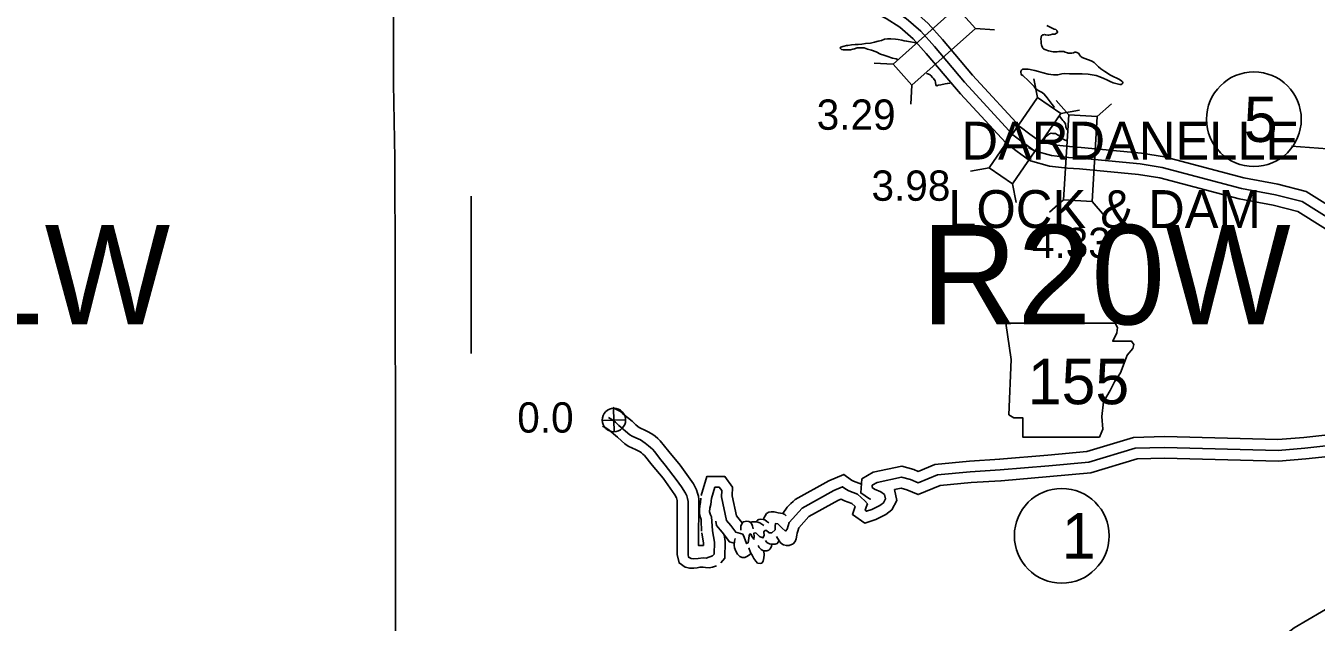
# Model space of a CAD drawing. Extents: x 31699 to 244310, y -8841 to 11474.
# Drawn here: x 94816 to 96015, y 3295 to 3849 of the extents above; entities that cross this region are included whole.
import ezdxf

# ---------------------------------------------------------------- set-up
doc = ezdxf.new("R2010")
doc.units = 0
for name, color, linetype in [('B_Logo', 7, 'Continuous'), ('Default', 7, 'Continuous'), ('G-ANNO-TEXT', 7, 'Continuous'), ('Level 21', 7, 'Continuous'), ('Level 55', 7, 'Continuous'), ('R_Border', 7, 'Continuous'), ('R_Border Notes', 7, 'Continuous'), ('R_Draft', 7, 'Continuous'), ('R_Logo', 7, 'Continuous'), ('R_XS_EARTHWORK_STAGE1', 7, 'Continuous'), ('R_XS_EARTHWORK_STAGE2', 7, 'Continuous'), ('S_WALL', 7, 'Continuous'), ('S_WALL_ANNOT', 7, 'Continuous')]:
    doc.layers.add(name, color=color, linetype=linetype)

msp = doc.modelspace()

# ---------------------------------------------------------------- linework, layer by layer
at = {"layer": 'B_Logo'}
for points in [[(95753.4, 3733), (95743, 3740.4), (95733.2, 3747.8), (95691.9, 3792.7), (95688.3, 3796.7), (95660.2, 3830.1), (95647.5, 3844.3), (95634.1, 3856), (95620.4, 3864.7), (95590.5, 3879.8), (95576.9, 3888.3), (95551.3, 3907.5), (95539.3, 3920.6), (95516.6, 3952.1), (95510.9, 3959.9), (95506.1, 3965.2), (95496.6, 3971.7), (95443.3, 3997.1)], [(95747.7, 3736.2), (95753.4, 3733), (95769.1, 3728.7), (95784.9, 3726.9), (95795.9, 3726.2), (95851.3, 3720.9), (95871.9, 3717.6), (95945.7, 3698.1), (95977.2, 3692.1), (96001.9, 3685.9), (96046.9, 3657.8)], [(95357.4, 3485.3), (95360.6, 3483.3), (95364, 3480.7), (95367.2, 3477.8), (95377.4, 3469), (95379.3, 3467.8), (95383, 3466.2), (95387.2, 3464.3), (95391.6, 3461.4), (95394.6, 3458.9), (95398.4, 3455.7), (95400.6, 3453.1), (95404.9, 3447.3), (95410.2, 3440.8), (95420.3, 3427.6), (95425.3, 3420.7), (95429.1, 3414.7), (95430.1, 3412.4), (95431, 3410), (95431.4, 3407), (95431.6, 3357.7), (95431.9, 3355.2), (95434.4, 3354), (95436.6, 3353.8), (95440.8, 3354.2), (95445.5, 3354.8), (95448.1, 3354.5), (95454.1, 3356.6)], [(95721.5, 3436.4), (95766.6, 3440.3), (95803.7, 3443.5), (95846.9, 3456.7), (95873.9, 3457.4), (95979.7, 3454.5), (96004.5, 3456.6), (96049, 3461.5), (96069.2, 3461.7), (96138.5, 3454.2), (96224.1, 3446.2), (96261.8, 3440.7), (96280.3, 3437.6)], [(95721.5, 3436.4), (95693.6, 3434.6), (95663.1, 3431.8), (95645.2, 3424.3), (95637.9, 3427.4), (95629.8, 3429.7), (95607, 3424.8), (95602.4, 3422.2), (95602.3, 3420.1), (95604.6, 3418.5), (95610.4, 3416.1), (95614, 3413.5), (95614.9, 3409.5), (95612.9, 3405.9), (95609.7, 3403.4), (95602, 3399.5), (95597.3, 3398), (95596, 3398.9), (95596.9, 3401.7), (95598, 3404.9), (95595.5, 3407.8), (95588.8, 3414), (95580.8, 3416.9), (95578, 3418.4), (95574.8, 3420.8), (95566.7, 3417.2), (95537.3, 3401), (95525.3, 3387.5), (95523.6, 3381.4), (95521.9, 3379.6), (95518.6, 3382.7), (95514.9, 3386.2), (95512.6, 3386.5), (95512.2, 3384.4), (95512.4, 3380.8), (95509.3, 3378.1), (95506.8, 3378.1), (95504.2, 3380), (95502.8, 3380.1), (95501.9, 3379), (95502.2, 3375.5), (95500.9, 3373.2), (95497.6, 3374.6), (95494.4, 3377.9), (95492.5, 3377.8), (95492.9, 3374.6), (95492.6, 3372), (95490.7, 3374.4), (95490.1, 3376.5), (95488.9, 3377), (95488, 3375.3), (95487.2, 3368.7), (95485.8, 3368), (95483.5, 3374), (95482.2, 3376.8), (95475.7, 3378.5), (95471, 3384.7), (95467.2, 3389.4), (95462.5, 3411.3), (95462.6, 3417.2), (95460.3, 3420.4), (95456.3, 3420.4), (95453.1, 3409.9)], [(95453.1, 3410.2), (95452.4, 3404.4), (95451.6, 3400.9), (95451.2, 3397.4), (95452.2, 3394.6), (95453, 3392.8), (95454, 3380)], [(95454, 3379.7), (95455.9, 3369.3), (95455.5, 3358.2), (95454.1, 3356.6)]]:
    msp.add_lwpolyline(points, dxfattribs=at)
at = {"layer": 'Default'}
msp.add_line((95229.9, 3691), (95229.9, 3544.7), dxfattribs=at)
at = {"layer": 'G-ANNO-TEXT'}
msp.add_lwpolyline([(95726.6, 3572.9), (95731.7, 3539), (95729.5, 3487.7), (95734, 3484.9), (95742.4, 3484.9), (95742.4, 3466.9), (95813.5, 3466.9), (95816.9, 3474.2), (95815.7, 3486), (95817.4, 3499.6), (95823.6, 3510.3), (95827.6, 3518.2), (95833.2, 3526.6), (95836.6, 3535.7), (95839.4, 3543), (95844.5, 3549.2), (95845.6, 3553.1), (95843.4, 3556), (95825.9, 3556), (95829.8, 3563.9), (95830.4, 3568.9), (95828.1, 3572.8)], close=True, dxfattribs=at)
at = {"layer": 'Level 21'}
for p, q in [((95362.7, 3471.9), (95362.2, 3493.6)), ((95351.6, 3482.5), (95373.3, 3483))]:
    msp.add_line(p, q, dxfattribs=at)
msp.add_circle((95362.5, 3482.8), 10.9, dxfattribs=at)
at = {"layer": 'Level 55'}
for points in [[(95445.7, 3366.2), (95444.2, 3366.2), (95441.4, 3366.1), (95441.2, 3366.1), (95441.5, 3409), (95441.2, 3412.1), (95440.2, 3414.7), (95439.2, 3417.9), (95436.5, 3423.5), (95424, 3440.9), (95413.6, 3453.6), (95405.5, 3463.4), (95403.2, 3465.6), (95400.9, 3467.8), (95397.8, 3470), (95393.8, 3472.2), (95390.6, 3473.8), (95387.9, 3474.9), (95386.1, 3475.8), (95384.7, 3476.7), (95382.9, 3478.3), (95379.3, 3481.8), (95370.9, 3488.7), (95368.1, 3491), (95364.3, 3493), (95361.4, 3494.6)], [(95457.7, 3347.3), (95456, 3346.6), (95454.2, 3346.1), (95451, 3345.5), (95447.6, 3345.8), (95445.5, 3346.1), (95444.1, 3346.2), (95443.7, 3346.2), (95442.2, 3345.9), (95439.8, 3345.4), (95436.8, 3345), (95433, 3345.1), (95428.8, 3346.1), (95423, 3350), (95421.2, 3357.9), (95421.4, 3407.8), (95421.3, 3408.1), (95420.6, 3410.5), (95419.2, 3413.3), (95408.2, 3428.7), (95398.1, 3440.9), (95390.8, 3449.8), (95389.5, 3451.1), (95388.2, 3452.3), (95387, 3453.1), (95384.5, 3454.5), (95382.6, 3455.5), (95379.7, 3456.6), (95375.8, 3458.6), (95372.6, 3460.7), (95369.4, 3463.5), (95365.9, 3466.9), (95358.1, 3473.3), (95356.9, 3474.3), (95354.9, 3475.4), (95351.8, 3477)], [(95720.9, 3446.4), (95692.9, 3444.6), (95660.7, 3441.6), (95645.2, 3435.1), (95641.2, 3436.8), (95630.1, 3440), (95603.3, 3434.3), (95592.8, 3428.1), (95591.9, 3415.1), (95599.8, 3409.6), (95601.3, 3409.1)], [(95481.7, 3387.2), (95481.6, 3387.3), (95478.9, 3390.8), (95476.5, 3393.8), (95472.5, 3412.4), (95472.6, 3420.3), (95465.6, 3430.3), (95448.9, 3430.4), (95443.5, 3412.8)], [(95592.4, 3423.3), (95585, 3426.1), (95583.3, 3426.9), (95576, 3432.2), (95562.3, 3426.2), (95530.9, 3408.9)], [(95722.1, 3426.4), (95694.4, 3424.7), (95665.6, 3422), (95645.2, 3413.5), (95634.6, 3417.9), (95629.4, 3419.4), (95623.2, 3418.1), (95625.5, 3408.1), (95620.7, 3399.3), (95615.1, 3394.9), (95605.8, 3390.2), (95595.6, 3387), (95584.1, 3395), (95586.6, 3402.4), (95583.5, 3405.3), (95576.7, 3407.8), (95573.7, 3409.4), (95571.1, 3408.3), (95543.6, 3393.1)], [(95443.1, 3410.1), (95442.9, 3406), (95442.2, 3403.2), (95442, 3399.7), (95442, 3396), (95442.8, 3392.2), (95443.5, 3390.5), (95443.7, 3389.5), (95444, 3379.5)], [(95530.9, 3408.9), (95528.9, 3407.2), (95526.9, 3405.3), (95523.6, 3401.7), (95519.4, 3395.9)], [(95522.5, 3393.7), (95521.3, 3394.9), (95519.4, 3395.9), (95515.1, 3396.7), (95511.3, 3397.5), (95508.8, 3397.6), (95506.3, 3397.1), (95504.2, 3395.9), (95503, 3393.9), (95501.8, 3391.6), (95501.5, 3390.3)], [(95543.6, 3393.1), (95534.3, 3382.6)], [(95474.3, 3368.5), (95469.8, 3369.7), (95463.1, 3378.5), (95457.9, 3384.9), (95457.1, 3388.8)], [(95489, 3387.9), (95487.7, 3388.6), (95486.1, 3388.7), (95484.5, 3388.6), (95482.7, 3388.1), (95481.2, 3386.3), (95480.5, 3384.2), (95480.4, 3383), (95480.4, 3380.3)], [(95489, 3387.9), (95489.7, 3387.3), (95490.7, 3385.9), (95491.4, 3384.1), (95492, 3381.7)], [(95501.7, 3384.7), (95499.9, 3386.1), (95498.1, 3387.2), (95496.3, 3387.8), (95494.6, 3388.1), (95492.6, 3388.2), (95490.7, 3388.2), (95489.3, 3387.9)], [(95506.3, 3387.3), (95504.7, 3388.6), (95502.7, 3390.1), (95501.3, 3390.5), (95499.1, 3390.8), (95497.2, 3390.5), (95495.8, 3389.8), (95494.7, 3388.6), (95494.5, 3388)], [(95534.3, 3382.6), (95533.4, 3379.6), (95532.7, 3377.7), (95532.3, 3375.9), (95531.9, 3372.5), (95530.9, 3369.8), (95528.9, 3367.8), (95525.4, 3366.3), (95522.8, 3366.1), (95520.2, 3366.7), (95517.6, 3368.5), (95515.9, 3370.4), (95513.4, 3374.4)], [(95444.1, 3377.9), (95445.8, 3368.5), (95445.8, 3366.2)], [(95464.8, 3376.1), (95465.9, 3370), (95465.4, 3354.4), (95461.7, 3350.1)], [(95489.9, 3358.9), (95488.8, 3357.7), (95486.6, 3356.2), (95484.1, 3355.1), (95481.6, 3355.1), (95479.5, 3356.1), (95477.4, 3358.2), (95475.7, 3361), (95474.6, 3363.9), (95474.3, 3366.6), (95474.5, 3370.3), (95475.1, 3372.6)], [(95515.8, 3370.5), (95515.2, 3369.3), (95514.3, 3368.1), (95512.4, 3367.4), (95510.8, 3367.4), (95508.3, 3367.3), (95506.9, 3367.8), (95504.6, 3369.1), (95503.4, 3370.9)], [(95501.9, 3361), (95502, 3357.4), (95501.8, 3354.8), (95501.1, 3351.7), (95499.9, 3349.9), (95498.4, 3349.6), (95496, 3349.9), (95494.3, 3351.5), (95492.4, 3354.1), (95490.9, 3357.1), (95489.5, 3359.8), (95487.9, 3364)], [(95509.1, 3367.2), (95508.8, 3365.5), (95508.4, 3364), (95507.4, 3362.7), (95506.3, 3361.8), (95504.5, 3361.1), (95502.6, 3361.1), (95500.8, 3361.6), (95499.3, 3362.5), (95497.4, 3364.4), (95496.6, 3366.3)]]:
    msp.add_lwpolyline(points, dxfattribs=at)
at = {"layer": 'R_Border Notes'}
for centre in [(95957.1, 3762.4), (95778.6, 3375.2)]:
    msp.add_circle(centre, 44, dxfattribs=at)
at = {"layer": 'R_Draft'}
msp.add_line((95992.1, 3737.5), (96213, 3720.7), dxfattribs=at)
for points in [[(95764.8, 3849.4), (95771.6, 3846.1), (95773, 3845.7), (95774, 3844.8), (95774.1, 3844.5), (95774.5, 3843.7), (95774.5, 3843.3), (95774.3, 3842.8), (95773.7, 3842.3), (95772, 3841.6), (95770, 3841.3), (95767.8, 3840.7), (95766.5, 3840.5), (95765.6, 3840.6), (95763.6, 3840.9), (95762.6, 3841), (95761.7, 3840.9), (95761.3, 3840.9), (95760.9, 3840.8), (95760.6, 3840.8), (95760.3, 3840.5), (95760.1, 3840.1), (95759.8, 3839.5), (95759.5, 3838.9), (95759.4, 3838.3), (95759.1, 3836.7), (95759.3, 3834.9), (95759.4, 3833.1), (95759.7, 3831.3), (95760.1, 3830.5), (95760.6, 3829.2), (95760.9, 3828.5), (95761.6, 3827.8), (95762.8, 3827.1), (95766.4, 3825.9), (95770.6, 3825.1), (95774.3, 3824.9), (95775.9, 3825.2), (95777.6, 3825.4), (95779.1, 3825.4), (95780.4, 3825.3), (95781.7, 3824.7), (95783.9, 3824.1), (95784.5, 3823.9), (95787.8, 3823.9), (95789.5, 3824.2), (95790.2, 3824.4), (95790.8, 3824.6), (95791.7, 3824.7), (95792.5, 3824.4), (95793.1, 3824.2), (95794.1, 3823.8), (95794.7, 3823), (95795.2, 3822.1), (95796.1, 3821.1), (95797.7, 3819.8), (95800, 3818.8), (95802.6, 3818), (95804.4, 3817.4), (95806.6, 3816.4), (95808.8, 3815.1), (95811.3, 3812.7), (95812.8, 3811), (95814.8, 3809.3), (95818.5, 3806.8), (95820.1, 3805.8), (95823.4, 3803.8), (95827.1, 3801.9), (95829.7, 3800.6), (95832.2, 3799.2), (95834.3, 3797.9), (95835.1, 3797.3), (95835.3, 3796.5), (95835.2, 3796), (95835, 3795.5), (95834.6, 3795.2), (95833.7, 3794.7), (95832.6, 3794.8), (95830.2, 3795.2), (95826.3, 3796.2), (95823.7, 3797.5), (95820.5, 3799), (95817.6, 3800.4)], [(95643.1, 3833.4), (95642.8, 3833.4), (95641.6, 3833.7), (95638.1, 3834.3), (95636.1, 3834.6), (95634.5, 3834.8), (95632.1, 3835.3), (95630, 3835.8), (95626.7, 3836.4), (95624, 3836.8), (95619.8, 3837.2), (95616.8, 3837.2), (95613.8, 3836.7), (95611.1, 3835.7), (95607.9, 3834.9), (95604.6, 3833.9), (95600.8, 3833.1), (95596.1, 3832.7), (95592.7, 3832.2), (95589.5, 3831.8), (95586.6, 3831.7), (95583.1, 3831.4), (95579.8, 3831), (95578.6, 3830.8), (95576.5, 3830.3), (95575.1, 3830.1), (95573.2, 3829.3), (95572.8, 3828.5), (95573, 3828), (95573.5, 3827.6), (95573.8, 3827.3), (95575.4, 3826.9), (95577, 3826.8), (95579.6, 3826.8), (95582.2, 3826.9), (95584.4, 3827.5), (95585.9, 3827.9), (95588.5, 3828.7), (95591.5, 3828.9), (95594.9, 3828.8), (95598, 3827.6), (95601.8, 3826.7), (95606.1, 3825), (95610.2, 3822.9), (95613.2, 3821.8), (95616.1, 3820.9), (95621.3, 3819.3), (95624.8, 3818.4), (95626.5, 3817.7)], [(95653, 3804.9), (95654, 3804.7)], [(95654, 3804.7), (95656.3, 3803.8), (95657, 3803), (95658.4, 3801.3), (95659.4, 3800.3), (95660.9, 3798.2), (95661.4, 3796.8), (95661.4, 3796.1), (95661.5, 3794.8), (95661.9, 3793.7), (95662.7, 3793.5), (95663.8, 3793.9), (95666.3, 3794.5), (95670.2, 3795.2), (95672.4, 3795.6), (95674.7, 3795.8), (95674.9, 3795.8)], [(95817.6, 3800.4), (95813.9, 3801.9), (95810.7, 3802.9), (95806.7, 3803.8), (95803.2, 3804.3), (95797.6, 3804.7), (95792.8, 3804.6), (95789.3, 3804.7), (95785.7, 3804.7), (95781.2, 3804.9), (95778.7, 3804.6), (95774.9, 3803.7), (95771, 3803.6), (95765.9, 3804.3), (95761.4, 3805.6), (95757.1, 3806.8), (95753.5, 3807.6), (95750.6, 3808.2), (95749.2, 3808.5), (95747.5, 3808.8), (95746.6, 3808.9), (95744.7, 3808.9), (95743.6, 3809), (95742.2, 3808.8), (95741.7, 3808.6), (95741.2, 3808.1), (95740.8, 3807.5), (95740.6, 3806.8), (95740.6, 3805.7), (95740.9, 3804.5), (95741.3, 3803.6), (95742.4, 3803), (95747.8, 3798), (95750.8, 3795.1), (95752.9, 3792.8), (95754.1, 3791.1), (95756.6, 3789), (95758.5, 3788.2), (95760.5, 3787.2), (95762.3, 3785.8), (95765, 3782.3), (95767.7, 3778.6), (95769.7, 3776.1), (95771.7, 3773.2)], [(95776.3, 3765.9), (95777.5, 3764.1), (95778.8, 3762.4), (95779.7, 3761.3), (95780.5, 3760.2), (95781.4, 3758.9), (95782, 3758), (95782.2, 3757.4), (95782.3, 3756.4), (95782.5, 3755.1), (95782.7, 3754.4), (95783, 3753.8), (95783.7, 3752.7), (95783.7, 3752.6), (95784.6, 3752.1)], [(95761, 3741.7), (95761.2, 3742), (95761.6, 3742.8), (95762.2, 3743.9), (95762.8, 3744.8), (95763.3, 3745.6), (95763.6, 3746), (95764.8, 3747.1), (95765.8, 3747.7), (95766.4, 3748.3), (95767.3, 3748.7), (95768.7, 3749.3), (95770, 3749.1), (95771.3, 3749.2), (95772.9, 3749), (95774.5, 3748), (95775.8, 3747.4), (95776.4, 3746.7), (95777.4, 3745.9), (95778.9, 3744.6), (95781.2, 3743.2), (95783.4, 3742.2), (95783.7, 3741.9)]]:
    msp.add_lwpolyline(points, dxfattribs=at)
at = {"layer": 'R_Logo'}
for points in [[(95158.9, 3726), (95157.8, 3795.4), (95157.7, 3970.6), (95157.2, 4052.5)], [(94211.4, 3269.1), (94282.2, 3268.3), (94455.7, 3266.6), (94631.7, 3267.5), (94803.9, 3263), (94981.5, 3269.3), (95159.6, 3270.3), (95159.5, 3445.2), (95159.2, 3622.5), (95158.9, 3726)]]:
    msp.add_lwpolyline(points, dxfattribs=at)
at = {"layer": 'R_XS_EARTHWORK_STAGE1'}
for p, q in [((95698.5, 3846.6), (95716.1, 3845.6)), ((95621.8, 3813.6), (95604.3, 3814.6)), ((95639.4, 3793.9), (95638.4, 3776.3)), ((95756, 3782.6), (95752.7, 3799.9)), ((95785.2, 3766.6), (95773.5, 3779.8)), ((95811.5, 3765), (95824.7, 3776.6)), ((95777.7, 3767.7), (95795, 3770.9)), ((95711.2, 3717.3), (95693.9, 3714.1)), ((95732.9, 3702.4), (95736.1, 3685.1)), ((95780.3, 3687.5), (95767.1, 3675.9)), ((95806.7, 3685.9), (95818.3, 3672.7))]:
    msp.add_line(p, q, dxfattribs=at)
for points in [[(95680.9, 3866.3), (95621.8, 3813.6), (95639.4, 3793.9), (95698.5, 3846.6)], [(95732.9, 3702.4), (95777.7, 3767.7), (95756, 3782.6), (95711.2, 3717.3)], [(95785.2, 3766.6), (95780.3, 3687.5), (95806.7, 3685.9), (95811.5, 3765)]]:
    msp.add_lwpolyline(points, close=True, dxfattribs=at)
at = {"layer": 'R_XS_EARTHWORK_STAGE2'}
for points in [[(95757.7, 3742.2), (95749, 3748.5), (95740, 3755.3), (95699.3, 3799.4), (95695.8, 3803.2), (95667.7, 3836.6), (95654.5, 3851.4), (95640.1, 3864), (95625.3, 3873.4), (95595.4, 3888.5), (95582.6, 3896.5), (95558, 3914.9), (95547.1, 3926.9), (95524.7, 3958), (95518.7, 3966.3), (95512.8, 3972.8), (95501.6, 3980.4), (95447.6, 4006.2)], [(95747.5, 3724.9), (95737.1, 3732.4), (95726.5, 3740.4), (95684.4, 3785.9), (95680.7, 3790.2), (95652.6, 3823.5), (95640.5, 3837.1), (95628, 3847.9), (95615.4, 3856), (95585.6, 3871), (95571.3, 3880), (95544.5, 3900), (95531.5, 3914.2), (95508.5, 3946.2), (95503.1, 3953.6), (95499.5, 3957.6), (95491.6, 3963), (95439, 3988.1)], [(96051.9, 3666.5), (96005.8, 3695.2), (95979.3, 3701.9), (95947.9, 3707.8), (95874, 3727.4), (95852.6, 3730.9), (95796.7, 3736.2), (95785.8, 3736.9), (95771, 3738.6), (95757.8, 3742.2)], [(96041.9, 3649.1), (95997.9, 3676.6), (95975, 3682.4), (95943.5, 3688.3), (95869.8, 3707.8), (95850, 3711), (95795.1, 3716.3), (95784, 3717), (95767.3, 3718.9), (95749.5, 3723.7), (95747.5, 3724.8)], [(95720.7, 3446.4), (95765.8, 3450.2), (95801.8, 3453.4), (95845.3, 3466.6), (95873.9, 3467.4), (95979.4, 3464.6), (96003.6, 3466.6), (96048.4, 3471.5), (96069.7, 3471.7), (96139.5, 3464.2), (96225.3, 3456.1), (96263.3, 3450.5), (96264.7, 3450.3)], [(95722.4, 3426.4), (95767.5, 3430.3), (95805.6, 3433.6), (95848.5, 3446.7), (95873.9, 3447.4), (95980, 3444.5), (96005.5, 3446.7), (96049.6, 3451.5), (96068.7, 3451.7), (96137.5, 3444.3), (96222.9, 3436.2), (96260.3, 3430.8), (96272.3, 3428.8)], [(96202.3, 3382.1), (96170.8, 3375.2), (96154.9, 3369.9), (96124, 3358.5), (96108.2, 3350.9), (96088, 3337.9), (96078.2, 3331.9), (96032.5, 3312.1), (95994.5, 3289.6), (95981.7, 3279.8), (95968.5, 3267.6), (95942.2, 3241.5), (95919.7, 3217.7), (95903.8, 3201.4), (95891.7, 3191.5), (95885.3, 3186.6), (95873.2, 3179), (95869.3, 3176.7), (95858.8, 3167.5), (95852.3, 3158.8), (95833, 3121.8)]]:
    msp.add_lwpolyline(points, dxfattribs=at)

# ---------------------------------------------------------------- texts
at = {"layer": 'G-ANNO-TEXT'}
msp.add_text('155', height=42.24, dxfattribs=at).set_placement((95747, 3497.5))
at = {"layer": 'R_Border'}
for s, p in [('R21W', (94606.9, 3571.7)), ('R20W', (95648, 3571.7))]:
    msp.add_text(s, height=92.4, dxfattribs=at).set_placement(p)
at = {"layer": 'R_Border Notes'}
for s, p in [('5', (95947.7, 3741.3)), ('1', (95778.6, 3354.1))]:
    msp.add_text(s, height=42.2, dxfattribs=at).set_placement(p)
at = {"layer": 'R_Draft'}
for s, p in [('DARDANELLE', (95685.4, 3724.9)), ('LOCK & DAM', (95673.1, 3661.3))]:
    msp.add_text(s, height=35.2, dxfattribs=at).set_placement(p)
at = {"layer": 'S_WALL'}
for s, p in [('3.29', (95550.9, 3752.6)), ('3.98', (95601.8, 3686.6)), ('4.33', (95750.9, 3633.4))]:
    msp.add_text(s, height=28.16, dxfattribs=at).set_placement(p)
at = {"layer": 'S_WALL_ANNOT'}
msp.add_text('0.0', height=28.16, dxfattribs=at).set_placement((95272.7, 3471.1))

doc.saveas('drawing.dxf')
